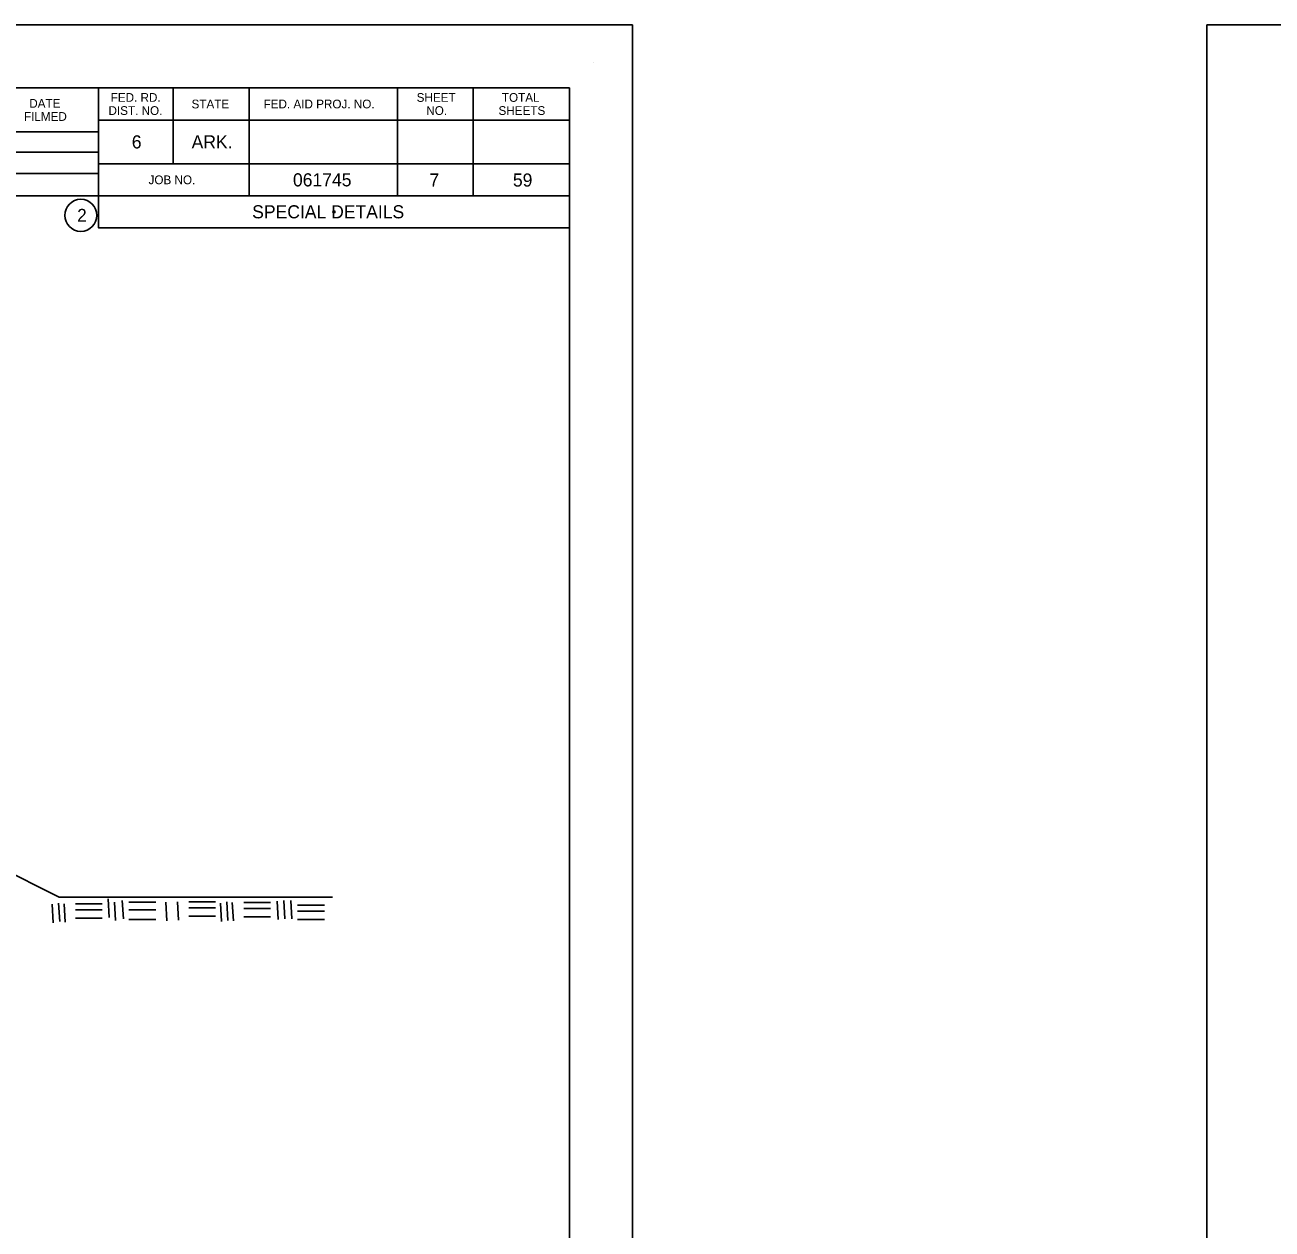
# Model space of a CAD drawing. Extents: x 438659 to 573674, y 10724 to 98600.
# Drawn here: x 519895 to 533589, y 65801 to 79030 of the extents above; entities that cross this region are included whole.
import ezdxf

# ---------------------------------------------------------------- set-up
doc = ezdxf.new("R2010")
doc.units = 0
for name, color, linetype in [('R_Striping', 7, 'Continuous'), ('T_Vehicle Path Lt Major', 7, 'Continuous'), ('T_Vehicle Path Rt', 7, 'Continuous')]:
    doc.layers.add(name, color=color, linetype=linetype)

msp = doc.modelspace()

# ---------------------------------------------------------------- linework, layer by layer
at = {"layer": 'R_Striping'}
for p, q in [((526137, 78614), (526137, 78614)), ((487586, 78338), (525874, 78338)), ((520702, 78338), (520702, 76802)), ((521523, 78338), (521523, 77505)), ((522356, 78338), (522356, 77152)), ((523985, 78338), (523985, 77152)), ((524818, 78338), (524818, 77152)), ((525874, 53322), (525874, 78338)), ((525874, 77985), (520702, 77985)), ((525874, 77987), (525874, 77987)), ((516003, 77855), (520702, 77855)), ((516003, 77632), (520702, 77632)), ((516003, 77399), (520702, 77399)), ((525874, 77505), (520702, 77505)), ((521057, 77505), (525874, 77505)), ((525874, 77152), (516003, 77152)), ((520702, 76802), (525874, 76802))]:
    msp.add_line(p, q, dxfattribs=at)
for points in [[(526566, 79030), (485766, 79030), (485766, 52630), (526566, 52630)], [(573674, 79030), (532874, 79030), (532874, 52630), (573674, 52630)], [(487586, 53322), (487586, 78338), (516003, 78338), (516003, 77152), (520702, 77152), (520702, 76802), (525874, 76802), (525874, 53322)]]:
    msp.add_lwpolyline(points, close=True, dxfattribs=at)
msp.add_circle((520509, 76938), 176, dxfattribs=at)
at = {"layer": 'T_Vehicle Path Lt Major'}
msp.add_circle((523288, 76977), 12, dxfattribs=at)
at = {"layer": 'T_Vehicle Path Rt'}
for p, q in [((520270, 69449), (516545, 71311)), ((523273, 69449), (520270, 69449)), ((520194, 69369), (520206, 69166)), ((520264, 69383), (520276, 69180)), ((520325, 69376), (520336, 69173)), ((520743, 69376), (520449, 69376)), ((520743, 69309), (520449, 69309)), ((520809, 69428), (520820, 69225)), ((520878, 69393), (520889, 69190)), ((520964, 69411), (520976, 69208)), ((521332, 69394), (521037, 69394)), ((521332, 69307), (521037, 69307)), ((521440, 69391), (521452, 69188)), ((521571, 69398), (521582, 69195)), ((521989, 69398), (521695, 69398)), ((521989, 69331), (521695, 69331)), ((522041, 69382), (522053, 69179)), ((522112, 69397), (522122, 69193)), ((522172, 69389), (522184, 69186)), ((522590, 69389), (522297, 69389)), ((522590, 69322), (522297, 69322)), ((522665, 69404), (522676, 69201)), ((522737, 69412), (522748, 69209)), ((522814, 69412), (522826, 69209)), ((523183, 69359), (522889, 69359)), ((520743, 69218), (520449, 69218)), ((521332, 69203), (521037, 69203)), ((521989, 69240), (521695, 69240)), ((522590, 69232), (522297, 69232)), ((523183, 69292), (522889, 69292)), ((523183, 69201), (522889, 69201))]:
    msp.add_line(p, q, dxfattribs=at)

# ---------------------------------------------------------------- texts
at = {"layer": 'R_Striping'}
for s, height, p in [('DATE', 96, (519942, 78120)), ('FED. RD.', 96, (520836, 78185)), ('STATE', 96, (521724, 78113)), ('FED. AID PROJ. NO.', 96, (522515, 78113)), ('SHEET', 96, (524196, 78185)), ('TOTAL', 96, (525132, 78185)), ('FILMED', 96, (519884, 77976)), ('DIST. NO.', 96, (520812, 78041)), ('NO.', 96, (524302, 78041)), ('SHEETS', 96, (525095, 78041)), ('6', 144, (521068, 77673)), ('ARK.', 144, (521725, 77673)), ('JOB NO.', 96, (521252, 77280)), ('061745', 144, (522838, 77256)), ('7', 144, (524336, 77254)), ('59', 144, (525253, 77254)), ('2', 141, (520468, 76868)), ('SPECIAL DETAILS', 144, (522390, 76905))]:
    msp.add_text(s, height=height, dxfattribs=at).set_placement(p)

doc.saveas('drawing.dxf')
